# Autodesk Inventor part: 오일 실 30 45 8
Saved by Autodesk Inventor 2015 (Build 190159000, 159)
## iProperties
Created: 2026-07
Part Number: 오일 실 30 45 8
Material: 일반
Document SubType Name: Modeling
Designer: USER
Density: 1 g/cm^3
Appearance: 기본값
Author: USER
Author: jhkim
Creation Date: 2026-07-01
Sending System: Autodesk Inventor 2027
Preprocessor: ST-DEVELOPER v20.1
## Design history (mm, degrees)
node "오일 실 30 45 81"
body "Solid1"
node "기준1"
